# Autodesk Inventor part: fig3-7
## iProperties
Created: 2005-02
Part Number: fig3-7
Document SubType Name: Modeling
Designer: CADCIM
Manufacturer: Standard
Standards Organization: Custom
Author: CADCIM
